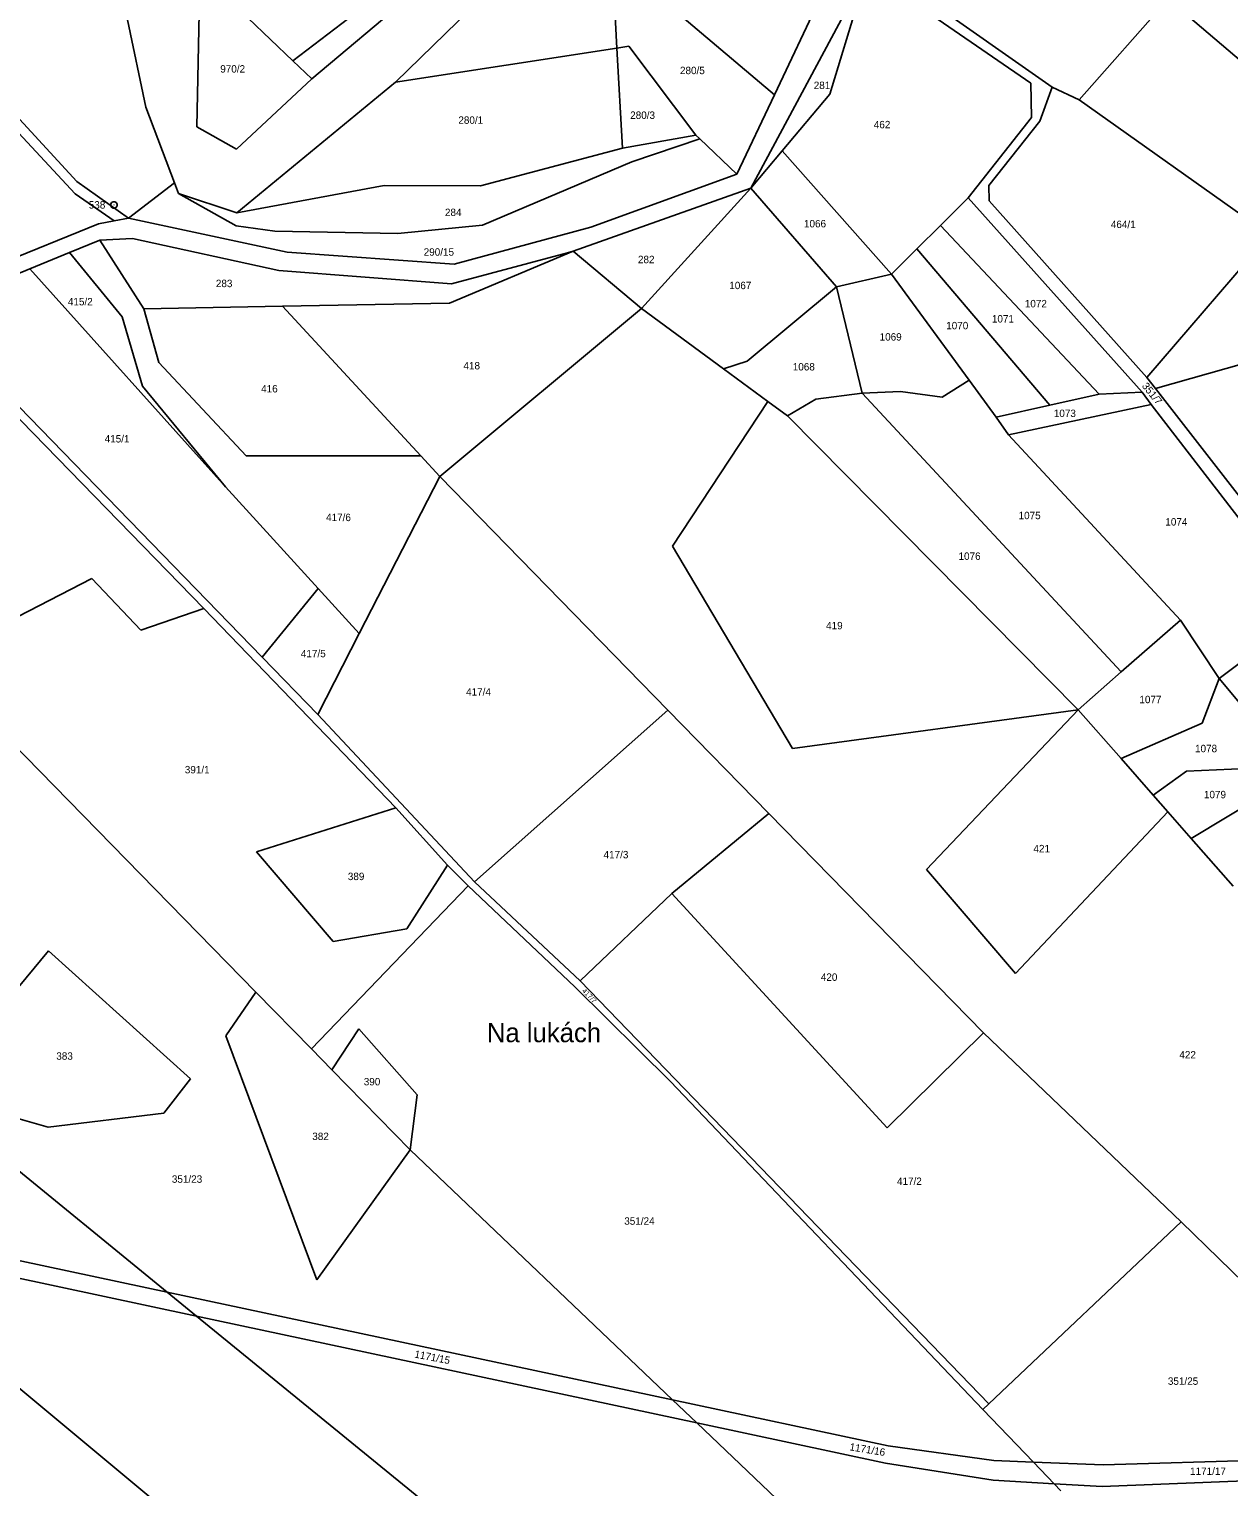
# Model space of a CAD drawing. Extents: x -593358 to -590116, y -1072518 to -1068420.
# Drawn here: x -592265.8 to -591991, y -1071558 to -1071223.8 of the extents above; entities that cross this region are included whole.
import ezdxf

# ---------------------------------------------------------------- set-up
doc = ezdxf.new("R2010")
doc.units = 0
for name, color, linetype in [('Názvosloví', 7, 'Continuous'), ('Parcela KN', 7, 'Continuous'), ('Parcela ZE', 7, 'Continuous'), ('Parcelní číslo', 7, 'Continuous'), ('Vrstva 17', 7, 'Continuous'), ('Vrstva 24', 7, 'Continuous')]:
    doc.layers.add(name, color=color, linetype=linetype)

msp = doc.modelspace()

# ---------------------------------------------------------------- linework, layer by layer
at = {"layer": 'Parcela KN'}
for p, q in [((-592205.37, -1071231.06), (-592143.26, -1071183.61)), ((-592201.05, -1071235.19), (-592153.7, -1071195.35)), ((-592181.89, -1071235.99), (-592148.34, -1071203.19)), ((-592095.06, -1071238.85), (-592079.5, -1071205.91)), ((-592131.15, -1071228.15), (-592132.3, -1071207.31)), ((-592095.06, -1071238.85), (-592132.3, -1071207.31)), ((-592100.44, -1071260.3), (-592073.73, -1071210.42)), ((-592082.38, -1071238.73), (-592073.73, -1071210.42)), ((-592036.33, -1071236.23), (-592073.73, -1071210.42)), ((-592031.43, -1071237.1), (-592072.6, -1071208.21)), ((-592226.65, -1071210.68), (-592227.4, -1071246.21)), ((-592205.37, -1071231.06), (-592226.65, -1071210.68)), ((-592243.24, -1071221.68), (-592239.02, -1071241.74)), ((-592181.89, -1071235.99), (-592131.15, -1071228.15)), ((-592131.15, -1071228.15), (-592128.42, -1071227.73)), ((-592129.88, -1071251.11), (-592131.15, -1071228.15)), ((-592128.42, -1071227.73), (-592113.08, -1071248.12)), ((-592201.05, -1071235.19), (-592205.37, -1071231.06)), ((-592218.25, -1071251.33), (-592201.05, -1071235.19)), ((-592218.23, -1071265.91), (-592181.89, -1071235.99)), ((-592036.17, -1071244.07), (-592036.33, -1071236.23)), ((-592031.43, -1071237.1), (-592034.28, -1071244.91)), ((-592103.66, -1071257.07), (-592095.06, -1071238.85)), ((-592093.26, -1071251.72), (-592082.38, -1071238.73)), ((-592239.02, -1071241.74), (-592232.47, -1071259.07)), ((-592227.4, -1071246.21), (-592218.25, -1071251.33)), ((-592050.64, -1071262.48), (-592036.17, -1071244.07)), ((-592034.28, -1071244.91), (-592045.97, -1071259.65)), ((-592113.08, -1071248.12), (-592129.88, -1071251.11)), ((-592127.68, -1071254.22), (-592112.17, -1071248.98)), ((-592112.17, -1071248.98), (-592113.08, -1071248.12)), ((-592103.66, -1071257.07), (-592112.17, -1071248.98)), ((-592162.39, -1071259.75), (-592129.88, -1071251.11)), ((-592100.44, -1071260.3), (-592093.26, -1071251.72)), ((-592068.25, -1071279.99), (-592093.26, -1071251.72)), ((-592161.89, -1071268.76), (-592127.68, -1071254.22)), ((-592137.13, -1071269.18), (-592103.66, -1071257.07)), ((-592243.06, -1071267.14), (-592232.47, -1071259.07)), ((-592232.47, -1071259.07), (-592231.54, -1071261.53)), ((-592218.23, -1071265.91), (-592184.48, -1071259.69)), ((-592184.48, -1071259.69), (-592162.39, -1071259.75)), ((-592141.16, -1071274.68), (-592100.44, -1071260.3)), ((-592100.44, -1071260.3), (-592080.85, -1071282.88)), ((-592045.97, -1071259.65), (-592045.86, -1071263.15)), ((-592231.54, -1071261.53), (-592218.23, -1071265.91)), ((-592231.54, -1071261.53), (-592218.33, -1071268.9)), ((-592057.01, -1071268.82), (-592050.64, -1071262.48)), ((-592010.84, -1071307.07), (-592050.64, -1071262.48)), ((-592045.86, -1071263.15), (-592009.73, -1071303.65)), ((-592246.3, -1071267.75), (-592243.06, -1071267.14)), ((-592243.06, -1071267.14), (-592206.71, -1071274.96)), ((-592276.85, -1071279.38), (-592249.91, -1071268.43)), ((-592249.91, -1071268.43), (-592246.3, -1071267.75)), ((-592218.33, -1071268.9), (-592209.49, -1071270.13)), ((-592209.49, -1071270.13), (-592181.32, -1071270.67)), ((-592181.32, -1071270.67), (-592161.89, -1071268.76)), ((-592168.4, -1071277.71), (-592137.13, -1071269.18)), ((-592062.4, -1071274.18), (-592057.01, -1071268.82)), ((-592249.58, -1071272.18), (-592256.56, -1071275.05)), ((-592242.08, -1071271.78), (-592249.58, -1071272.18)), ((-592242.08, -1071271.78), (-592208.55, -1071279.14)), ((-592256.56, -1071275.05), (-592265.59, -1071278.78)), ((-592206.71, -1071274.96), (-592168.4, -1071277.71)), ((-592169.06, -1071282.17), (-592142.42, -1071275.12)), ((-592142.42, -1071275.12), (-592141.16, -1071274.68)), ((-592068.25, -1071279.99), (-592062.4, -1071274.18)), ((-592265.59, -1071278.78), (-592288.15, -1071288.07)), ((-592208.55, -1071279.14), (-592169.06, -1071282.17)), ((-592080.85, -1071282.88), (-592068.25, -1071279.99)), ((-592009.73, -1071303.65), (-592007.75, -1071306.19)), ((-592008.72, -1071309.86), (-592010.84, -1071307.07)), ((-592007.75, -1071306.19), (-591987.97, -1071331.66)), ((-591972.38, -1071357.06), (-592008.72, -1071309.86)), ((-592234.13, -1071513.33), (-592300.36, -1071499.2)), ((-592270.64, -1071509.59), (-592227.41, -1071518.82)), ((-592118.37, -1071538.02), (-592234.13, -1071513.33)), ((-592227.41, -1071518.82), (-592112.86, -1071543.27)), ((-592069.02, -1071548.55), (-592118.37, -1071538.02)), ((-592112.86, -1071543.27), (-592069.57, -1071552.51)), ((-592044.78, -1071551.91), (-592069.02, -1071548.55)), ((-591952.99, -1071550.93), (-592019.78, -1071552.9)), ((-592069.57, -1071552.51), (-592044.96, -1071556.41)), ((-592035.74, -1071552.27), (-592044.78, -1071551.91)), ((-592019.78, -1071552.9), (-592035.74, -1071552.27)), ((-592044.96, -1071556.41), (-592030.98, -1071557.24)), ((-592030.98, -1071557.24), (-592019.98, -1071557.9)), ((-592019.98, -1071557.9), (-591954.09, -1071555.18))]:
    msp.add_line(p, q, dxfattribs=at)
at = {"layer": 'Parcela ZE'}
for p, q in [((-592004.88, -1071216.91), (-592025.24, -1071240.02)), ((-592004.88, -1071216.91), (-591914.91, -1071293.58)), ((-592287.4, -1071227.12), (-592255.21, -1071261.54)), ((-592284.83, -1071226.19), (-592254.89, -1071258.76)), ((-592025.24, -1071240.02), (-592031.43, -1071237.1)), ((-592025.24, -1071240.02), (-591981.68, -1071271)), ((-592254.89, -1071258.76), (-592243.06, -1071267.14)), ((-592125.47, -1071287.86), (-592100.44, -1071260.3)), ((-592255.21, -1071261.54), (-592246.3, -1071267.75)), ((-592020.68, -1071307.47), (-592057.01, -1071268.82)), ((-592249.58, -1071272.18), (-592239.5, -1071287.95)), ((-591981.68, -1071271), (-592009.73, -1071303.65)), ((-592256.56, -1071275.05), (-592244.51, -1071289.74)), ((-592169.46, -1071286.61), (-592141.16, -1071274.68)), ((-592141.16, -1071274.68), (-592125.47, -1071287.86)), ((-592031.93, -1071309.98), (-592062.4, -1071274.18)), ((-592265.59, -1071278.78), (-592220.77, -1071328.77)), ((-592050.44, -1071304.31), (-592068.25, -1071279.99)), ((-592080.85, -1071282.88), (-592101.33, -1071299.94)), ((-592080.85, -1071282.88), (-592074.97, -1071307.23)), ((-592239.5, -1071287.95), (-592207.72, -1071287.34)), ((-592207.72, -1071287.34), (-592169.46, -1071286.61)), ((-592207.72, -1071287.34), (-592176.08, -1071321.62)), ((-592291.03, -1071289.54), (-592225.8, -1071356.59)), ((-592244.51, -1071289.74), (-592239.81, -1071305.68)), ((-592239.5, -1071287.95), (-592236.05, -1071300.25)), ((-592171.73, -1071326.34), (-592125.47, -1071287.86)), ((-592125.47, -1071287.86), (-592106.75, -1071301.68)), ((-592284.13, -1071293.87), (-592212.42, -1071367.75)), ((-592236.05, -1071300.25), (-592216.03, -1071321.62)), ((-592101.33, -1071299.94), (-592106.75, -1071301.68)), ((-592007.75, -1071306.19), (-591982.67, -1071299.08)), ((-592106.75, -1071301.68), (-592096.58, -1071309.18)), ((-592239.81, -1071305.68), (-592220.77, -1071328.77)), ((-592074.97, -1071307.23), (-592085.56, -1071308.63)), ((-592074.97, -1071307.23), (-592066.17, -1071306.88)), ((-592074.97, -1071307.23), (-592015.6, -1071371.16)), ((-592066.17, -1071306.88), (-592056.61, -1071308.16)), ((-592056.61, -1071308.16), (-592050.44, -1071304.31)), ((-592044.28, -1071312.73), (-592050.44, -1071304.31)), ((-592031.93, -1071309.98), (-592020.68, -1071307.47)), ((-592020.68, -1071307.47), (-592010.84, -1071307.07)), ((-592118.39, -1071342.37), (-592096.58, -1071309.18)), ((-592096.58, -1071309.18), (-592092.05, -1071312.49)), ((-592085.56, -1071308.63), (-592092.05, -1071312.49)), ((-592044.28, -1071312.73), (-592031.93, -1071309.98)), ((-592041.4, -1071316.81), (-592008.72, -1071309.86)), ((-592092.05, -1071312.49), (-592025.47, -1071379.82)), ((-592041.4, -1071316.81), (-592044.28, -1071312.73)), ((-592002.06, -1071359.27), (-592041.4, -1071316.81)), ((-592216.03, -1071321.62), (-592176.08, -1071321.62)), ((-592176.08, -1071321.62), (-592171.73, -1071326.34)), ((-592171.73, -1071326.34), (-592190.16, -1071362.32)), ((-592171.73, -1071326.34), (-592119.46, -1071379.89)), ((-592220.77, -1071328.77), (-592199.57, -1071352.01)), ((-592090.88, -1071388.68), (-592118.39, -1071342.37)), ((-592288.09, -1071368.59), (-592251.4, -1071349.73)), ((-592251.4, -1071349.73), (-592240.22, -1071361.61)), ((-592199.57, -1071352.01), (-592212.42, -1071367.75)), ((-592199.57, -1071352.01), (-592190.16, -1071362.32)), ((-592240.22, -1071361.61), (-592225.8, -1071356.59)), ((-592225.8, -1071356.59), (-592181.8, -1071402.31)), ((-591993.2, -1071372.7), (-591972.38, -1071357.06)), ((-592015.6, -1071371.16), (-592002.06, -1071359.27)), ((-592002.06, -1071359.27), (-591993.2, -1071372.7)), ((-592190.16, -1071362.32), (-592199.67, -1071380.89)), ((-592288.09, -1071368.59), (-592213.83, -1071444.58)), ((-592212.42, -1071367.75), (-592199.67, -1071380.89)), ((-592025.47, -1071379.82), (-592015.6, -1071371.16)), ((-591997.1, -1071382.89), (-591993.2, -1071372.7)), ((-591993.2, -1071372.7), (-591979.13, -1071389.5)), ((-592199.67, -1071380.89), (-592163.77, -1071419.28)), ((-592163.77, -1071419.28), (-592119.46, -1071379.89)), ((-592119.46, -1071379.89), (-592096.32, -1071403.59)), ((-592025.47, -1071379.82), (-592090.88, -1071388.68)), ((-592025.47, -1071379.82), (-592060.2, -1071416.43)), ((-592025.47, -1071379.82), (-592015.63, -1071391.04)), ((-592015.63, -1071391.04), (-591997.1, -1071382.89)), ((-592015.63, -1071391.04), (-592008.31, -1071399.39)), ((-592008.31, -1071399.39), (-592000.63, -1071393.91)), ((-592000.63, -1071393.91), (-591976.31, -1071392.87)), ((-591999.58, -1071409.34), (-591974.93, -1071394.51)), ((-592008.31, -1071399.39), (-592004.93, -1071403.24)), ((-592181.8, -1071402.31), (-592213.71, -1071412.37)), ((-592181.8, -1071402.31), (-592169.92, -1071415.46)), ((-592118.58, -1071421.98), (-592096.32, -1071403.59)), ((-592096.32, -1071403.59), (-592047.13, -1071453.9)), ((-592039.81, -1071440.29), (-592004.93, -1071403.24)), ((-592004.93, -1071403.24), (-591999.58, -1071409.34)), ((-591999.58, -1071409.34), (-591990, -1071420.26)), ((-592213.71, -1071412.37), (-592196.11, -1071432.98)), ((-592179.3, -1071430.05), (-592169.92, -1071415.46)), ((-592169.92, -1071415.46), (-592165.24, -1071420.19)), ((-592060.2, -1071416.43), (-592039.81, -1071440.29)), ((-592165.24, -1071420.19), (-592201.11, -1071457.59)), ((-592165.24, -1071420.19), (-592140.77, -1071443.37)), ((-592163.77, -1071419.28), (-592139.59, -1071441.99)), ((-592139.59, -1071441.99), (-592118.58, -1071421.98)), ((-592118.58, -1071421.98), (-592069.19, -1071475.63)), ((-592196.11, -1071432.98), (-592179.3, -1071430.05)), ((-592271.56, -1071447.46), (-592261.35, -1071435.07)), ((-592261.35, -1071435.07), (-592228.84, -1071464.43)), ((-592140.77, -1071443.37), (-592118.85, -1071465.03)), ((-592139.59, -1071441.99), (-592045.96, -1071538.93)), ((-592220.69, -1071454.58), (-592213.83, -1071444.58)), ((-592213.83, -1071444.58), (-592201.11, -1071457.59)), ((-592190.22, -1071453), (-592196.45, -1071462.36)), ((-592176.93, -1071468.12), (-592190.22, -1071453)), ((-592069.19, -1071475.63), (-592047.13, -1071453.9)), ((-592047.13, -1071453.9), (-592001.88, -1071497.2)), ((-592199.85, -1071510.48), (-592220.69, -1071454.58)), ((-592201.11, -1071457.59), (-592196.45, -1071462.36)), ((-592228.84, -1071464.43), (-592234.92, -1071472.31)), ((-592196.45, -1071462.36), (-592178.52, -1071480.71)), ((-592118.85, -1071465.03), (-592047.3, -1071540.2)), ((-592178.52, -1071480.71), (-592176.93, -1071468.12)), ((-592261.42, -1071475.54), (-592271.56, -1071472.61)), ((-592234.92, -1071472.31), (-592261.42, -1071475.54)), ((-592234.13, -1071513.33), (-592277.39, -1071478)), ((-592178.52, -1071480.71), (-592199.85, -1071510.48)), ((-592178.52, -1071480.71), (-592118.37, -1071538.02)), ((-592045.96, -1071538.93), (-592001.88, -1071497.2)), ((-592001.88, -1071497.2), (-591984.65, -1071514.02)), ((-592227.41, -1071518.82), (-592234.13, -1071513.33)), ((-592139.81, -1071590.36), (-592227.41, -1071518.82)), ((-592268.57, -1071534.86), (-592221.13, -1071574.43)), ((-592118.37, -1071538.02), (-592112.86, -1071543.27)), ((-592047.3, -1071540.2), (-592045.96, -1071538.93)), ((-592047.3, -1071540.2), (-592035.74, -1071552.27)), ((-592112.86, -1071543.27), (-592081.95, -1071572.73)), ((-592035.74, -1071552.27), (-592030.98, -1071557.24)), ((-592030.98, -1071557.24), (-592029.42, -1071558.87))]:
    msp.add_line(p, q, dxfattribs=at)
at = {"layer": 'Vrstva 24'}
msp.add_line((-592246.42, -1071264.1), (-592246.32, -1071264.1), dxfattribs=at)
msp.add_lwpolyline([(-592246.18, -1071263.38), (-592245.84, -1071263.57), (-592245.65, -1071263.91), (-592245.65, -1071264.3), (-592245.84, -1071264.64), (-592246.18, -1071264.83), (-592246.57, -1071264.83), (-592246.91, -1071264.64), (-592247.1, -1071264.3), (-592247.1, -1071263.91), (-592246.91, -1071263.57), (-592246.57, -1071263.38)], close=True, dxfattribs=at)

# ---------------------------------------------------------------- texts
at = {"layer": 'Názvosloví'}
msp.add_text('Na lukách', height=4.4, dxfattribs=at).set_placement((-592160.926, -1071456.04))
at = {"layer": 'Parcelní číslo'}
for s, p in [('970/2', (-592222.003, -1071233.78)), ('280/5', (-592116.687, -1071234.14)), ('281', (-592086.047, -1071237.55)), ('280/1', (-592167.462, -1071245.52)), ('280/3', (-592128.097, -1071244.39)), ('462', (-592072.288, -1071246.55)), ('284', (-592170.535, -1071266.66)), ('1066', (-592088.282, -1071269.26)), ('464/1', (-592017.985, -1071269.42)), ('290/15', (-592175.402, -1071275.75)), ('282', (-592126.318, -1071277.47)), ('283', (-592223.012, -1071282.96)), ('1067', (-592105.392, -1071283.42)), ('415/2', (-592256.906, -1071287.14)), ('1072', (-592037.696, -1071287.59)), ('1071', (-592045.234, -1071291.07)), ('1069', (-592070.952, -1071295.21)), ('1070', (-592055.699, -1071292.62)), ('418', (-592166.286, -1071301.82)), ('1068', (-592090.852, -1071302.06)), ('416', (-592212.636, -1071307.1)), ('1073', (-592031.049, -1071312.73)), ('415/1', (-592248.484, -1071318.57)), ('417/6', (-592197.765, -1071336.59)), ('1075', (-592039.119, -1071336.15)), ('1074', (-592005.502, -1071337.61)), ('1076', (-592052.882, -1071345.47)), ('419', (-592083.216, -1071361.39)), ('417/5', (-592203.532, -1071367.8)), ('417/4', (-592165.685, -1071376.59)), ('1077', (-592011.442, -1071378.33)), ('1078', (-591998.702, -1071389.57)), ('391/1', (-592230.124, -1071394.41)), ('1079', (-591996.662, -1071400.12)), ('421', (-592035.71, -1071412.51)), ('417/3', (-592134.192, -1071413.89)), ('389', (-592192.778, -1071418.88)), ('420', (-592084.425, -1071441.97)), ('383', (-592259.565, -1071460.06)), ('422', (-592002.291, -1071459.77)), ('390', (-592189.128, -1071465.93)), ('382', (-592200.922, -1071478.46)), ('351/23', (-592233.089, -1071488.26)), ('417/2', (-592066.979, -1071488.76)), ('351/24', (-592129.452, -1071497.88)), ('351/25', (-592004.919, -1071534.57)), ('1171/17', (-591999.839, -1071555.23))]:
    msp.add_text(s, height=1.7, dxfattribs=at).set_placement(p)
for s, height, rotation, p in [('351/7', 1.7, 308.93884, (-592010.968, -1071305.667)), ('417/7', 1.14, 313.92358, (-592139.238, -1071444.359)), ('1171/15', 1.7, 349.10318, (-592177.615, -1071528.302)), ('1171/16', 1.7, 350.65017, (-592077.935, -1071549.571))]:
    msp.add_text(s, height=height, rotation=rotation, dxfattribs=at).set_placement(p)
at = {"layer": 'Vrstva 17'}
msp.add_text('538', height=1.7, dxfattribs=at).set_placement((-592252.124, -1071264.95))

doc.saveas('drawing.dxf')
